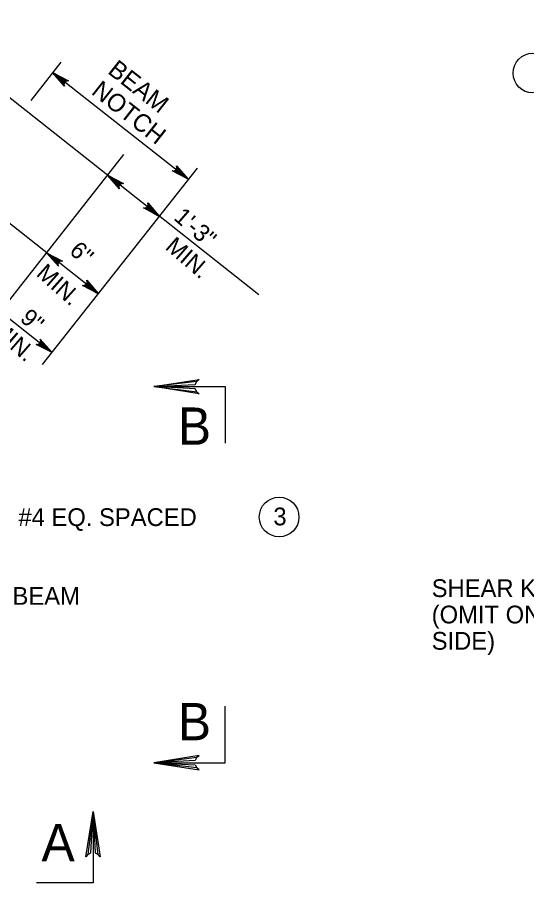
# Model space of a CAD drawing. Extents: x 639331 to 643089, y 299088 to 300975.
# Drawn here: x 640900.5 to 640986.5, y 300645 to 300791.1 of the extents above; entities that cross this region are included whole.
import ezdxf

# ---------------------------------------------------------------- set-up
doc = ezdxf.new("R2010")
doc.units = 0
doc.layers.add('1', color=7, linetype='Continuous')

msp = doc.modelspace()

# ---------------------------------------------------------------- linework, layer by layer
at = {"layer": '1'}
for p, q in [((640941.27, 300744.25), (640881.99, 300791.07)), ((640902.89, 300777.05), (640907.95, 300783.47)), ((640929.36, 300763.74), (640906.49, 300781.74)), ((640823.35, 300646.89), (640918.52, 300767.94)), ((640914.17, 300744.46), (640885.05, 300767.46)), ((640904.8, 300732.46), (640930.94, 300765.63)), ((640906.42, 300734.46), (640881.3, 300754.21)), ((640923.58, 300728.76), (640935.59, 300728.76)), ((640935.59, 300728.76), (640935.59, 300719.21)), ((640935.59, 300665.29), (640935.59, 300674.85)), ((640923.58, 300665.29), (640935.59, 300665.29)), ((640913.32, 300657.04), (640913.32, 300645.04)), ((640913.32, 300645.04), (640903.76, 300645.04))]:
    msp.add_line(p, q, dxfattribs=at)
for points in [[(640906.49, 300781.74), (640909.18, 300780.33), (640909.04, 300780.34), (640908.9, 300780.35), (640908.79, 300780.31), (640908.68, 300780.27), (640908.61, 300780.2), (640908.53, 300780.13), (640908.48, 300780.04), (640908.43, 300779.95), (640908.42, 300779.84), (640908.4, 300779.72), (640908.44, 300779.59), (640908.49, 300779.45), (640906.49, 300781.74), (640908.44, 300779.59), (640908.4, 300779.72), (640906.49, 300781.74), (640908.42, 300779.84), (640908.43, 300779.95), (640906.49, 300781.74), (640908.48, 300780.04), (640908.53, 300780.13), (640906.49, 300781.74), (640908.61, 300780.2), (640908.68, 300780.27), (640906.49, 300781.74), (640908.79, 300780.31), (640908.9, 300780.35), (640906.49, 300781.74), (640909.04, 300780.34)], [(640929.36, 300763.74), (640926.67, 300765.14), (640926.81, 300765.13), (640926.95, 300765.13), (640927.06, 300765.17), (640927.17, 300765.21), (640927.24, 300765.28), (640927.32, 300765.35), (640927.37, 300765.43), (640927.42, 300765.52), (640927.43, 300765.64), (640927.45, 300765.75), (640927.41, 300765.89), (640927.36, 300766.02), (640929.36, 300763.74), (640927.41, 300765.89), (640927.45, 300765.75), (640929.36, 300763.74), (640927.43, 300765.64), (640927.42, 300765.52), (640929.36, 300763.74), (640927.37, 300765.43), (640927.32, 300765.35), (640929.36, 300763.74), (640927.24, 300765.28), (640927.17, 300765.21), (640929.36, 300763.74), (640927.06, 300765.17), (640926.95, 300765.13), (640929.36, 300763.74), (640926.81, 300765.13)], [(640915.74, 300764.41), (640918.43, 300763.01), (640918.29, 300763.02), (640918.16, 300763.02), (640918.05, 300762.98), (640917.94, 300762.94), (640917.86, 300762.87), (640917.79, 300762.8), (640917.74, 300762.71), (640917.69, 300762.63), (640917.68, 300762.51), (640917.66, 300762.39), (640917.7, 300762.26), (640917.74, 300762.13), (640915.74, 300764.41), (640917.7, 300762.26), (640917.66, 300762.39), (640915.74, 300764.41), (640917.68, 300762.51), (640917.69, 300762.63), (640915.74, 300764.41), (640917.74, 300762.71), (640917.79, 300762.8), (640915.74, 300764.41), (640917.86, 300762.87), (640917.94, 300762.94), (640915.74, 300764.41), (640918.05, 300762.98), (640918.16, 300763.02), (640915.74, 300764.41), (640918.29, 300763.02)], [(640924.52, 300757.48), (640921.83, 300758.89), (640921.97, 300758.88), (640922.11, 300758.87), (640922.22, 300758.91), (640922.33, 300758.95), (640922.4, 300759.02), (640922.48, 300759.09), (640922.53, 300759.18), (640922.57, 300759.27), (640922.59, 300759.38), (640922.6, 300759.5), (640922.56, 300759.63), (640922.52, 300759.76), (640924.52, 300757.48), (640922.56, 300759.63), (640922.6, 300759.5), (640924.52, 300757.48), (640922.59, 300759.38), (640922.57, 300759.27), (640924.52, 300757.48), (640922.53, 300759.18), (640922.48, 300759.09), (640924.52, 300757.48), (640922.4, 300759.02), (640922.33, 300758.95), (640924.52, 300757.48), (640922.22, 300758.91), (640922.11, 300758.87), (640924.52, 300757.48), (640921.97, 300758.88)], [(640905.46, 300751.33), (640908.15, 300749.93), (640908.01, 300749.94), (640907.87, 300749.95), (640907.77, 300749.9), (640907.66, 300749.86), (640907.58, 300749.79), (640907.51, 300749.73), (640907.46, 300749.64), (640907.41, 300749.55), (640907.39, 300749.43), (640907.38, 300749.32), (640907.42, 300749.18), (640907.46, 300749.05), (640905.46, 300751.33), (640907.42, 300749.18), (640907.38, 300749.32), (640905.46, 300751.33), (640907.39, 300749.43), (640907.41, 300749.55), (640905.46, 300751.33), (640907.46, 300749.64), (640907.51, 300749.73), (640905.46, 300751.33), (640907.58, 300749.79), (640907.66, 300749.86), (640905.46, 300751.33), (640907.77, 300749.9), (640907.87, 300749.95), (640905.46, 300751.33), (640908.01, 300749.94)], [(640914.22, 300744.42), (640911.53, 300745.82), (640911.67, 300745.81), (640911.81, 300745.8), (640911.92, 300745.85), (640912.03, 300745.89), (640912.11, 300745.96), (640912.18, 300746.02), (640912.23, 300746.11), (640912.28, 300746.2), (640912.29, 300746.32), (640912.31, 300746.43), (640912.27, 300746.57), (640912.23, 300746.7), (640914.22, 300744.42), (640912.27, 300746.57), (640912.31, 300746.43), (640914.22, 300744.42), (640912.29, 300746.32), (640912.28, 300746.2), (640914.22, 300744.42), (640912.23, 300746.11), (640912.18, 300746.02), (640914.22, 300744.42), (640912.11, 300745.96), (640912.03, 300745.89), (640914.22, 300744.42), (640911.92, 300745.85), (640911.81, 300745.8), (640914.22, 300744.42), (640911.67, 300745.81)], [(640906.39, 300734.48), (640903.7, 300735.88), (640903.84, 300735.88), (640903.98, 300735.87), (640904.09, 300735.91), (640904.2, 300735.95), (640904.28, 300736.02), (640904.35, 300736.09), (640904.4, 300736.18), (640904.45, 300736.27), (640904.46, 300736.38), (640904.48, 300736.5), (640904.44, 300736.63), (640904.4, 300736.76), (640906.39, 300734.48), (640904.44, 300736.63), (640904.48, 300736.5), (640906.39, 300734.48), (640904.46, 300736.38), (640904.45, 300736.27), (640906.39, 300734.48), (640904.4, 300736.18), (640904.35, 300736.09), (640906.39, 300734.48), (640904.28, 300736.02), (640904.2, 300735.95), (640906.39, 300734.48), (640904.09, 300735.91), (640903.98, 300735.87), (640906.39, 300734.48), (640903.84, 300735.88)], [(640930.83, 300727.85), (640930.56, 300728.38), (640923.58, 300728.76), (640930.83, 300727.85), (640931.2, 300727.54), (640923.58, 300728.76), (640930.56, 300729.11), (640930.81, 300729.63), (640923.58, 300728.76), (640931.2, 300729.97), (640930.81, 300729.63)], [(640930.83, 300666.2), (640930.56, 300665.68), (640923.58, 300665.29), (640930.83, 300666.2), (640931.2, 300666.52), (640923.58, 300665.29), (640930.56, 300664.95), (640930.81, 300664.43), (640923.58, 300665.29), (640931.2, 300664.08), (640930.81, 300664.43)], [(640912.41, 300649.79), (640912.93, 300650.06), (640913.32, 300657.04), (640912.41, 300649.79), (640912.09, 300649.42), (640913.32, 300657.04), (640913.66, 300650.07), (640914.18, 300649.82), (640913.32, 300657.04), (640914.53, 300649.42), (640914.18, 300649.82)]]:
    msp.add_lwpolyline(points, dxfattribs=at)
for centre in [(640987.53, 300781.66), (640944.7, 300706.74)]:
    msp.add_circle(centre, 3.35, dxfattribs=at)

# ---------------------------------------------------------------- texts
for s, height, rotation, p in [('BEAM', 3, 321.796, (640915.61, 300781.74)), ('NOTCH', 3, 321.796, (640912.86, 300778.24)), ('1\'-3"', 2.875, 319.0163, (640926.75, 300757.05)), ('MIN.', 2.875, 319.0163, (640925.33, 300752.08)), ('6"', 2.875, 318.2384, (640909.14, 300751.39)), ('MIN.', 2.861, 318.3243, (640903.55, 300747.58)), ('9"', 2.875, 319.0163, (640900.81, 300739.98)), ('MIN.', 2.875, 319.0163, (640895.86, 300738.09))]:
    msp.add_text(s, height=height, rotation=rotation, dxfattribs=at).set_placement(p)
for s, height, p in [('B', 6.3, (640927.6, 300718.93)), ('#4 EQ. SPACED', 3, (640900.71, 300705.22)), ('3', 3, (640943.73, 300705.34)), ('SHEAR KEY (TYP.)', 3, (640970.44, 300693.24)), ('L BEAM', 3, (640896.37, 300691.93)), ('(OMIT ON FASCIA', 3, (640970.44, 300688.79)), ('SIDE)', 3, (640970.44, 300684.35)), ('B', 6.3, (640927.6, 300669.07)), ('A', 6.3, (640904.6, 300648.65))]:
    msp.add_text(s, height=height, dxfattribs=at).set_placement(p)

doc.saveas('drawing.dxf')
